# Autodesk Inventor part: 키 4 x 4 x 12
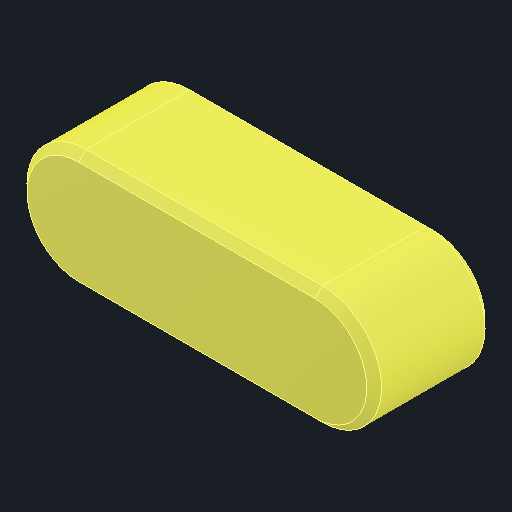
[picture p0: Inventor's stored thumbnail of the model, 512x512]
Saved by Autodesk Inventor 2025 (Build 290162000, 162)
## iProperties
Created: 2025-08
Part Number: 키 4 x 4 x 12
Material: 강철, 연강
Description: 키 및 해당 키홈
Document SubType Name: Modeling
Designer: infra027
Density: 7.85 g/cm^3
Appearance: 기본값
Author: jhkim
Sending System: Autodesk Inventor 2026
Preprocessor: ST-DEVELOPER v20.1
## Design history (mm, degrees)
feature "Solid1"
node "솔리드1"
